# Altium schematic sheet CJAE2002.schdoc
size 127 x 101 mm
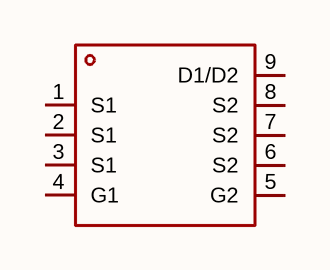
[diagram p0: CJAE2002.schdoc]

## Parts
Q?  cjae2002  [TDFN-8_L3.0-W3.0-P0.65-BL-EP2.3]  (value not drawn)

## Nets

Not connected (* = marked no-connect by the designer): Q? 1(S1) 2(S1) 3(S1) 4(G1) 5(G2) 6(S2) 7(S2) 8(S2) 9(D1/D2)

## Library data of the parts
Q? = cjae2002: 数量:2个N沟道;漏源电压(Vdss):18V;连续漏极电流(Id):15A;导通电阻(RDS(on)):4.4mΩ@4.5V;耗散功率(Pd):3W;阈值电压(Vgs(th)):1V;; Manufacturer: CJ(江苏长电/长晶); AddInBom: yes; ModelId: 87cbd0851a6d45bba9a717edfc43b2c9; ModelTransform: 118.11,118.8974,0,0,0,0,0,0,0; Number: 2个N沟道; Drain to Source Voltage: 18V; Current - Continuous Drain(Id): 15A; Pd - Power Dissipation: 3W; Gate Threshold Voltage (Vgs(th)): 1V; Gate Charge(Qg): 26.5nC@4.5V; Input Capacitance(Ciss): 1.97nF; Reverse Transfer Capacitance (Crss@Vds): 285pF; Configuration: 共漏; Type: N沟道; Output Capacitance(Coss): 315pF; Vgs: ±12V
